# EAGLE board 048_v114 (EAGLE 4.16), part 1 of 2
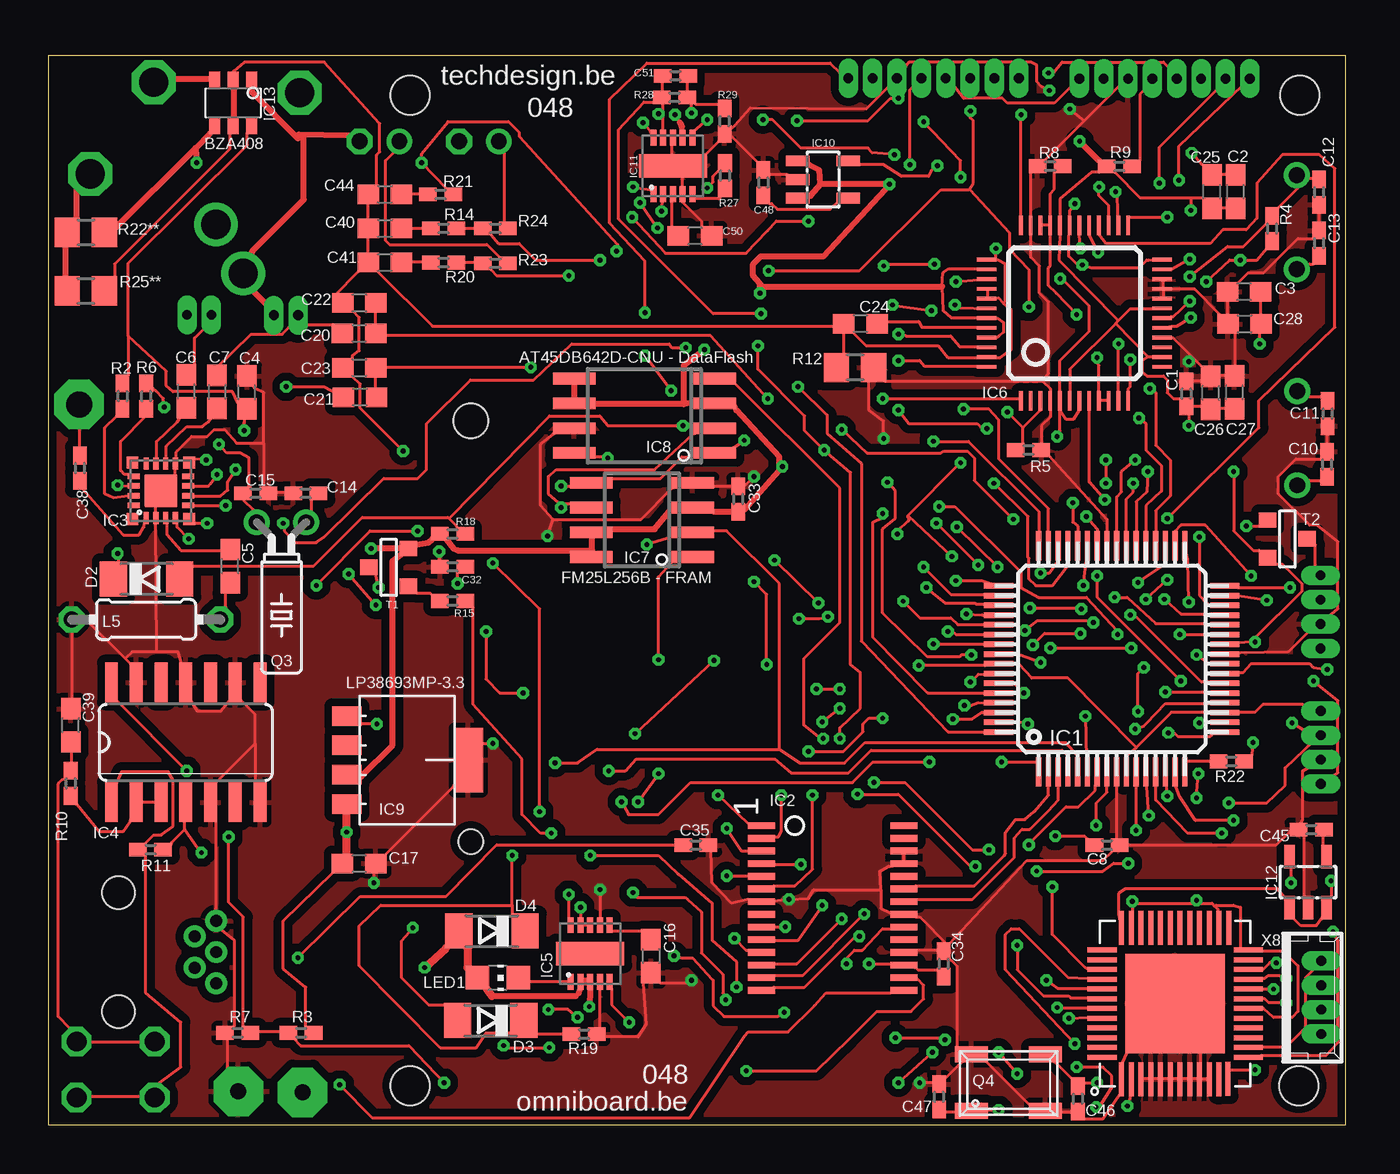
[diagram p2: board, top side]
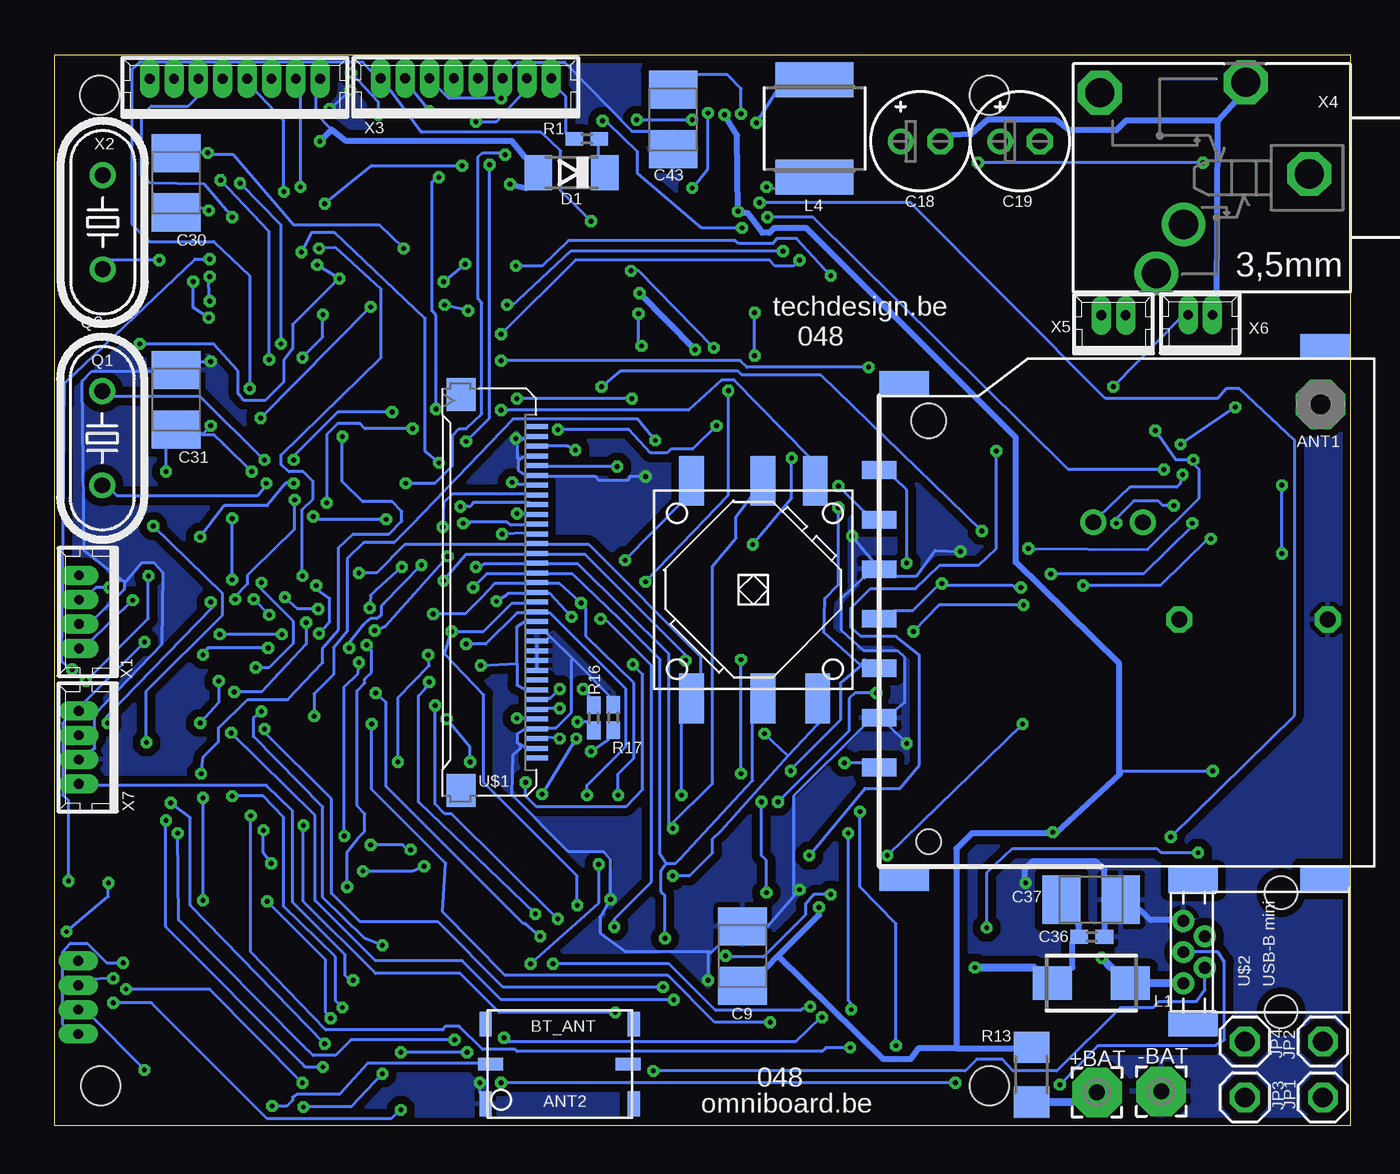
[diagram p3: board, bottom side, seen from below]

Size 66.5 x 54.9 mm. Coordinates in mm from the lower left corner, seen from the top.
Outline: 0,54.9 66.5,54.9 66.5,0 0,0 0,54.9
Copper layers (1*16): Top 0.0175mm / dielectric 1.55mm / Bottom 0.0175mm
Design rules "michel24": minimum track width 0.15mm, minimum drill 0.25mm, track to track 0.15mm, track to pad 0.15mm, pad to pad 0.2mm, via to via 0.2mm, smd to smd 0mil, copper to edge 0.25mm, drill to drill 0.1mm, minimum pad ring 10mil, minimum via ring 7mil, stop-mask expansion 2mil, vias tented up to drill 0mil, thermal gap 10mil
Holes 2 mm at 64.18,52.83 64.13,2.03 18.53,52.83 18.53,2.03

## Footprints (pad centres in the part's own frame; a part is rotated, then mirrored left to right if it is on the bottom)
2,54/0,8 = drill 0.813 pad 2.54 octagon: 1 0,0
PAD-01 = drill 1.321 pad 2.54 octagon: 1 0,0
BTANT_PAC = smd 1.27 x 0.635: P$1 0.7,-0.1; P$3 4.8,-0.1; P$4 4.8,7.5; P$6 0.7,7.5 | smd 0.635 x 1.27: P$2 2.75,0.15; P$5 2.75,7.2
C0402 = smd 0.9 x 0.7: 1 -0.65,0; 2 0.65,0
C0603 = smd 1.1 x 1: 1 -0.85,0; 2 0.85,0
B/3528-21R = smd 1.95 x 2.5: + 1.525,0; - -1.525,0
E2-5 = drill 0.813 pad 1.27 round: + -1.016,0 | drill 0.813 pad 1.27 octagon: - 1.016,0
SOD80C = smd 1.4 x 1.8: A 1.7,0; C -1.7,0
TQFP64-10X10 = smd 1.5 x 0.28: 1 -5.8,3.75; 2 -5.8,3.25; 3 -5.8,2.75; 4 -5.8,2.25; 5 -5.8,1.75; 6 -5.8,1.25; 7 -5.8,0.75; 8 -5.8,0.25; 9 -5.8,-0.25; 10 -5.8,-0.75; 11 -5.8,-1.25; 12 -5.8,-1.75; 13 -5.8,-2.25; 14 -5.8,-2.75; 15 -5.8,-3.25; 16 -5.8,-3.75; 33 5.8,-3.75; 34 5.8,-3.25; 35 5.8,-2.75; 36 5.8,-2.25; 37 5.8,-1.75; 38 5.8,-1.25; 39 5.8,-0.75; 40 5.8,-0.25; 41 5.8,0.25; 42 5.8,0.75; 43 5.8,1.25; 44 5.8,1.75; 45 5.8,2.25; 46 5.8,2.75; 47 5.8,3.25; 48 5.8,3.75 | smd 0.28 x 1.5: 17 -3.75,-5.8; 18 -3.25,-5.8; 19 -2.75,-5.8; 20 -2.25,-5.8; 21 -1.75,-5.8; 22 -1.25,-5.8; 23 -0.75,-5.8; 24 -0.25,-5.8; 25 0.25,-5.8; 26 0.75,-5.8; 27 1.25,-5.8; 28 1.75,-5.8; 29 2.25,-5.8; 30 2.75,-5.8; 31 3.25,-5.8; 32 3.75,-5.8; 49 3.75,5.8; 50 3.25,5.8; 51 2.75,5.8; 52 2.25,5.8; 53 1.75,5.8; 54 1.25,5.8; 55 0.75,5.8; 56 0.25,5.8; 57 -0.25,5.8; 58 -0.75,5.8; 59 -1.25,5.8; 60 -1.75,5.8; 61 -2.25,5.8; 62 -2.75,5.8; 63 -3.25,5.8; 64 -3.75,5.8
SSOP28DB = smd 0.348 x 1.397: 1 -4.225,-3.656; 2 -3.575,-3.656; 3 -2.925,-3.656; 4 -2.275,-3.656; 5 -1.625,-3.656; 6 -0.975,-3.656; 7 -0.325,-3.656; 8 0.325,-3.656; 9 0.975,-3.656; 10 1.625,-3.656; 11 2.275,-3.656; 12 2.925,-3.656; 13 3.575,-3.656; 14 4.225,-3.656; 15 4.225,3.656; 16 3.575,3.656; 17 2.925,3.656; 18 2.275,3.656; 19 1.625,3.656; 20 0.975,3.656; 21 0.325,3.656; 22 -0.325,3.656; 23 -0.975,3.656; 24 -1.625,3.656; 25 -2.275,3.656; 26 -2.925,3.656; 27 -3.575,3.656; 28 -4.225,3.656
QFN20-3X3 = smd 0.6 x 0.6: 1 -1.45,1.45; 6 -1.45,-1.45; 11 1.45,-1.45; 16 1.45,1.45 | smd 0.61 x 0.28: 2 -1.4,0.75; 3 -1.4,0.25; 4 -1.4,-0.25; 5 -1.4,-0.75; 12 1.4,-0.75; 13 1.4,-0.25; 14 1.4,0.25; 15 1.4,0.75 | smd 0.28 x 0.61: 7 -0.75,-1.4; 8 -0.25,-1.4; 9 0.25,-1.4; 10 0.75,-1.4; 17 0.75,1.4; 18 0.25,1.4; 19 -0.25,1.4; 20 -0.75,1.4 | smd 1.7 x 1.7: 21 0,0
SO14 = smd 0.66 x 2.032: 1 -3.81,-3.073; 2 -2.54,-3.073; 3 -1.27,-3.073; 4 0,-3.073; 5 1.27,-3.073; 6 2.54,-3.073; 7 3.81,-3.073; 8 3.81,3.073; 9 2.54,3.073; 10 1.27,3.073; 11 0,3.073; 12 -1.27,3.073; 13 -2.54,3.073; 14 -3.81,3.073
QFN10-3X3 = smd 0.813 x 0.305: 1 -1.45,1; 2 -1.45,0.5; 3 -1.45,0; 4 -1.45,-0.5; 5 -1.45,-1; 6 1.45,-1; 7 1.45,-0.5; 8 1.45,0; 9 1.45,0.5; 10 1.45,1 | smd 1.2 x 3.5: P$1 0,0
LQFP-48 = smd 0.2 x 1: 1 -2.75,-4.5; 2 -2.25,-4.5; 3 -1.75,-4.5; 4 -1.25,-4.5; 5 -0.75,-4.5; 6 -0.25,-4.5; 7 0.25,-4.5; 8 0.75,-4.5; 9 1.25,-4.5; 10 1.75,-4.5; 11 2.25,-4.5; 12 2.75,-4.5; 25 2.75,4.5; 26 2.25,4.5; 27 1.75,4.5; 28 1.25,4.5; 29 0.75,4.5; 30 0.25,4.5; 31 -0.25,4.5; 32 -0.75,4.5; 33 -1.25,4.5; 34 -1.75,4.5; 35 -2.25,4.5; 36 -2.75,4.5 | smd 1 x 0.2: 13 4.5,-2.75; 14 4.5,-2.25; 15 4.5,-1.75; 16 4.5,-1.25; 17 4.5,-0.75; 18 4.5,-0.25; 19 4.5,0.25; 20 4.5,0.75; 21 4.5,1.25; 22 4.5,1.75; 23 4.5,2.25; 24 4.5,2.75; 37 -4.5,2.75; 38 -4.5,2.25; 39 -4.5,1.75; 40 -4.5,1.25; 41 -4.5,0.75; 42 -4.5,0.25; 43 -4.5,-0.25; 44 -4.5,-0.75; 45 -4.5,-1.25; 46 -4.5,-1.75; 47 -4.5,-2.25; 48 -4.5,-2.75
SO-8 = smd 0.6 x 2.2: 1 -1.905,-2.6; 2 -0.635,-2.6; 3 0.635,-2.6; 4 1.905,-2.6; 5 1.905,2.6; 6 0.635,2.6; 7 -0.635,2.6; 8 -1.905,2.6
SO-8W = smd 0.6 x 2.2: 1 0.095,0.9; 2 1.365,0.9; 3 2.635,0.9; 4 3.905,0.9; 5 3.905,8.1; 6 2.635,8.1; 7 1.365,8.1; 8 0.095,8.1
SOT223-5 = smd 1 x 1.5: P$1 1.05,-0.65; P$2 2.55,-0.65; P$3 4.05,-0.65; P$4 5.55,-0.65 | smd 3.3 x 1.5: P$5 3.3,5.57
SOT23-5 = smd 0.55 x 1.2: 1 -0.95,-1.3; 2 0,-1.3; 3 0.95,-1.3; 4 0.95,1.3; 5 -0.95,1.3
SOT-457 = smd 0.55 x 0.8: 1 -0.95,-1.2; 2 0,-1.2; 3 0.95,-1.2; 4 0.95,1.2; 5 0,1.2; 6 -0.95,1.2
BGB203 = smd 1.75 x 0.25: 1 -3.88,2.75; 2 -3.88,2.25; 3 -3.88,1.75; 4 -3.88,1.25; 5 -3.88,0.75; 6 -3.88,0.25; 7 -3.88,-0.25; 8 -3.88,-0.75; 9 -3.88,-1.25; 10 -3.88,-1.75; 11 -3.88,-2.25; 12 -3.87,-2.71; 25 3.88,-2.75; 26 3.88,-2.25; 27 3.88,-1.75; 28 3.88,-1.25; 29 3.88,-0.75; 30 3.88,-0.25; 31 3.88,0.25; 32 3.88,0.75; 33 3.88,1.25; 34 3.88,1.75; 35 3.88,2.25; 36 3.88,2.75 | smd 0.25 x 1.5: 13 -2.75,-3.75; 14 -2.25,-3.75; 15 -1.75,-3.75; 16 -1.25,-3.75; 17 -0.75,-3.75; 18 -0.25,-3.75; 19 0.25,-3.75; 20 0.75,-3.75; 21 1.25,-3.75; 22 1.75,-3.75; 23 2.25,-3.75; 24 2.75,-3.75; 37 2.75,3.75; 38 2.25,3.75; 39 1.75,3.75; 40 1.25,3.75; 41 0.75,3.75; 42 0.25,3.75; 43 -0.25,3.75; 44 -0.75,3.75; 45 -1.25,3.75; 46 -1.75,3.75; 47 -2.25,3.75; 48 -2.75,3.75 | smd 5.1 x 5.1: 49 -0.002,0.007
1X01 = drill 1.016 octagon: 1 0,0
SM-B5 = smd 2 x 1.7: 1 -2,0; 2 2,0
L5650M = smd 1.8 x 4: 1 -2.5,0; 2 2.5,0
0204/7 = drill 0.813 octagon: 1 -3.81,0; 2 3.81,0
CHIP-LED0805 = smd 1.2 x 1.2: A 0,-1.05; C 0,1.05
HC49/S = drill 0.813 round: 1 -2.413,0; 2 2.413,0
TC26H = drill 0.813 round: 1 -1.27,0; 2 1.27,0
X-ABM3B_PACK = smd 1.676 x 0.813: P$1 0.6,0.2; P$2 4.4,0.2; P$3 4.4,3.1; P$4 0.6,3.1
R0402 = smd 0.9 x 0.7: 1 -0.65,0; 2 0.65,0
R0805 = smd 1.3 x 1.5: 1 -0.95,0; 2 0.95,0
R1206 = smd 1.6 x 1.8: 1 -1.4,0; 2 1.4,0
SOT-23 = smd 0.787 x 0.889: 1 0.025,-1.016; 2 -0.94,1.016; 3 0.991,1.016
XF2M-PAC = smd 1.1 x 0.25: 1 2.54,-8.52; 2 2.54,-8.02; 3 2.54,-7.52; 4 2.54,-7.02; 5 2.54,-6.52; 6 2.54,-6.02; 7 2.54,-5.52; 8 2.54,-5.02; 9 2.54,-4.52; 10 2.54,-4.02; 11 2.54,-3.52; 12 2.54,-3.02; 13 2.54,-2.52; 14 2.54,-2.02; 15 2.54,-1.52; 16 2.54,-1.02; 17 2.54,-0.52; 18 2.54,-0.02; 19 2.54,0.48; 20 2.54,0.98; 21 2.54,1.48; 22 2.54,1.98; 23 2.54,2.48; 24 2.54,2.98; 25 2.54,3.48; 26 2.54,3.98; 27 2.54,4.48; 28 2.54,4.98; 29 2.54,5.48; 30 2.54,5.98; 31 2.54,6.48; 32 2.54,6.98; 33 2.54,7.48; 34 2.54,7.98; 35 2.54,8.48 | smd 1.5 x 1.7: M1 -1.36,10.13; M2 -1.36,-10.17
USB-MINI-B-TH4 = drill 0.61 pad 1.016 round: P$1 1.448,8.51; P$2 2.248,7.41; P$3 3.048,8.51; P$4 3.848,7.41; P$5 4.648,8.51 | smd 1.27 x 2.54: P$8 -0.635,8.001; P$9 6.731,8.001 | hole 1.676: 0,3.5; 6.1,3.5
TACT2_PACK = smd 2.54 x 1.27: 1 -5.58,3.175; 2 -5.58,-0.5; 3 -5.58,-3.31; 4 5.58,-3.175; 5 5.58,-0.5; 6 5.58,3.175
MMC-SD-PACK3 = smd 1.27 x 2.54: P$1 -0.635,2.54; P$2 26.67,2.54; P$3 24.765,24.13; P$11 -0.635,24.13 | smd 0.914 x 1.778: P$4 20.32,25.4; P$5 17.78,25.4; P$6 15.24,25.4; P$7 12.7,25.4; P$8 10.16,25.4; P$9 7.62,25.4; P$10 5.08,25.4 | hole 1.27: 1.27,22.86 | hole 1.778: 22.86,22.86
53047-04 = drill 0.5 pad 0.698 long: 1 1.875,0.45; 2 0.625,0.45; 3 -0.625,0.45; 4 -1.875,0.45
53047-08 = drill 0.5 pad 0.698 long: 1 4.375,0.45; 2 3.125,0.45; 3 1.875,0.45; 4 0.625,0.45; 5 -0.625,0.45; 6 -1.875,0.45; 7 -3.125,0.45; 8 -4.375,0.45
PG203J = drill 1.499 octagon: 1 -5.004,-0.203; 4 5.74,-4.369; 5 -1.753,-4.902 | drill 1.499 round: 2 2.845,4.902; 3 1.448,2.388
53047-02 = drill 0.5 pad 0.698 long: 1 0.625,0.45; 2 -0.625,0.45

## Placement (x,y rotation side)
+BAT  [2,54/0,8]  13.02,1.68 270 bottom
-BAT  [2,54/0,8]  9.72,1.73 90 bottom
ANT1  [PAD-01]  1.56,36.97 0 bottom
ANT2  BT_ANT  [BTANT_PAC]  44.28,5.89 270 bottom
C1  100n  [C0402]  58.36,37.52 270 top
C2  100n  [C0603]  60.88,47.89 90 top
C3  100n  [C0603]  61.32,42.76 0 top
C4  100n  [C0603]  10.17,37.59 90 top
C5  470n  [C0603]  9.31,28.68 90 top
C6  330n  [C0603]  7.06,37.64 90 top
C7  330n  [C0603]  8.63,37.62 270 top
C8  100n  [C0402]  54.29,14.37 180 top
C9  4µ7/25V  [B/3528-21R]  31.2,8.68 270 bottom
C10  22p  [C0402]  65.58,33.9 270 top
C11  22p  [C0402]  65.6,36.51 90 top
C12  22p  [C0402]  65.17,47.86 90 top
C13  22p  [C0402]  65.17,45.25 270 top
C14  22p  [C0402]  13.19,32.42 0 top
C15  22p  [C0402]  10.62,32.41 180 top
C16  100n  [C0603]  30.89,8.67 270 top
C17  1µ  [C0603]  15.92,13.42 180 top
C18  100µ  [E2-5]  22.07,50.47 0 bottom
C19  100µ  [E2-5]  16.97,50.47 0 bottom
C20  1µ  [C0603]  15.92,40.62 0 top
C21  1µ  [C0603]  15.97,37.35 180 top
C22  10n  [C0603]  15.94,42.18 180 top
C23  10n  [C0603]  15.94,38.85 0 top
C24  1µ  [C0603]  41.64,41.12 0 top
C25  100n  [C0603]  59.67,47.89 90 top
C26  100n  [C0603]  59.61,37.57 90 top
C27  100n  [C0603]  60.83,37.59 90 top
C28  100n  [C0603]  61.34,41.1 0 top
C30  10µ  [B/3528-21R]  60.26,48.35 270 bottom
C31  10µ  [B/3528-21R]  60.25,37.2 270 bottom
C32  100n  [C0402]  20.72,28.64 180 top
C33  100n  [C0402]  35.37,32.12 90 top
C34  100n  [C0402]  45.91,8.27 270 top
C35  10n  [C0402]  33.19,14.36 0 top
C36  100n  [C0402]  13.29,9.66 0 bottom
C37  4µ7  [B/3528-21R]  13.31,11.57 180 bottom
C38  100p  [C0402]  1.6,33.7 90 top
C39  100n  [C0603]  1.13,20.51 90 top
C40  10n  [C0603]  17.25,46 0 top
C41  10n  [C0603]  17.25,44.25 0 top
C43  4µ7/25V  [B/3528-21R]  34.76,51.59 90 bottom
C44  47n  [C0603]  17.25,47.75 0 top
C45  10n  [C0402]  64.76,15.16 180 top
C46  6p7  [C0402]  52.79,1.36 270 top
C47  6p7  [C0402]  45.67,1.45 90 top
C48  10n  [C0402]  36.66,48.35 90 top
C50  47n  [C0603]  33.15,45.62 180 top
C51  33p  [C0402]  32.15,53.82 0 top
D1  1N4148  [SOD80C]  39.97,48.87 180 bottom
D2  1N4148  [SOD80C]  5.02,28.02 0 top
D3  1N4148  [SOD80C]  22.67,5.37 180 top
D4  1N4148  [SOD80C]  22.73,9.96 180 top
IC1  DSPIC33FJ256GP506/PT  [TQFP64-10X10]  54.53,23.92 90 top
IC2  FT245RL  [SSOP28DB]  40.22,11.14 270 top
IC3  SI4731  [QFN20-3X3]  5.75,32.54 90 top
IC4  74HC04D  [SO14]  7.03,19.64 0 top
IC5  MCP73855  [QFN10-3X3]  27.77,8.81 90 top
IC6  VS1053  [LQFP-48]  52.62,41.65 0 top
IC7  FM25L256B - FRAM  [SO-8]  30.43,31.05 90 top
IC8  AT45DB642D-CNU - DataFlash  [SO-8W]  35.06,34.39 90 top
IC9  LP38693MP-3.3  [SOT223-5]  15.95,22.03 270 top
IC10  LP2985IM5-1.8  [SOT23-5]  39.72,48.51 270 top
IC11  TPS61080  [QFN10-3X3]  32.02,49.21 90 top
IC12  LP2985IM5-2.8  [SOT23-5]  64.6,12.47 0 top
IC13  BZA408  [SOT-457]  9.46,52.44 180 top
IC14  BGB203_BLUETOOTHSMD  [BGB203]  57.78,6.24 90 top
JP1  [1X01]  1.43,1.42 180 bottom
JP2  [1X01]  1.43,4.29 180 bottom
JP3  [1X01]  5.43,1.42 180 bottom
JP4  [1X01]  5.43,4.29 180 bottom
L1  FERRITE BEAD  [SM-B5]  13.31,7.29 180 bottom
L4  4µH7  [L5650M]  27.5,51.14 90 bottom
L5  ferrite loop stick 180-600µH  [0204/7]  4.99,25.94 180 top
LED1  [CHIP-LED0805]  23.03,7.56 270 top
Q1  40MhZ  [HC49/S]  64.05,35.24 270 bottom
Q2  25MhZ  [HC49/S]  64.02,46.32 90 bottom
Q3  32768kHZ  [TC26H]  11.94,30.93 180 top
Q4  13MhZ  [X-ABM3B_PACK]  46.73,0.53 0 top
R1  10k  [R0402]  39.19,50.59 0 bottom
R2  10k  [R0402]  3.79,37.4 90 top
R3  470k  [R0402]  12.94,4.74 0 top
R4  1M  [R0402]  62.75,46 270 top
R5  100k  [R0402]  50.26,34.63 0 top
R6  2k2  [R0402]  5,37.4 90 top
R7  180k  [R0402]  9.69,4.74 0 top
R8  100k  [R0402]  51.37,49.2 180 top
R9  100k  [R0402]  54.92,49.18 180 top
R10  100k  [R0402]  1.13,17.54 90 top
R11  10k  [R0402]  5.22,14.13 180 top
R12  0R / 1206  [R0805]  41.36,38.87 180 top
R13  0R / 1206  [R1206]  16.37,2.59 270 bottom
R14  22R  [R0402]  20.25,46 0 top
R15  10k  [R0402]  20.72,26.89 0 top
R16  10k  [R0402]  38.83,20.9 90 bottom
R17  68k  [R0402]  37.83,20.91 270 bottom
R18  10k  [R0402]  20.71,30.33 180 top
R19  100k  [R0402]  27.46,4.67 0 top
R20  22R  [R0402]  20.25,44.25 0 top
R21  10R  [R0402]  20.1,47.75 0 top
R22  10k  [R0402]  60.66,18.66 180 top
R22**  0R  [R0805]  1.9,45.8 0 top
R23  10R  [R0402]  22.91,44.21 180 top
R24  10R  [R0402]  22.91,46.01 180 top
R25**  0R  [R0805]  1.9,42.8 0 top
R27  100R  [R0402]  34.69,48.7 270 top
R28  470k  [R0402]  32.1,52.72 180 top
R29  47k  [R0402]  34.67,51.51 90 top
T1  FMMT717  [SOT-23]  17.44,28.64 270 top
T2  FMMT717  [SOT-23]  63.54,30.05 90 top
U$1  OLED connector XF2M-3515-1  [XF2M-PAC]  44.28,27.35 0 bottom
U$2  USB-B mini  [USB-MINI-B-TH4]  0.08,5.83 90 bottom
U$3  TACT2_DEV  [TACT2_PACK]  30.65,27.47 90 bottom
U$4  SD-MMC socket  [MMC-SD-PACK3]  -1.21,13.28 90 bottom
X1  RS232-2  [53047-04]  64.79,26.33 90 bottom
X2  VS i/o  [53047-08]  57.24,53.24 0 bottom
X3  ICSP+  [53047-08]  45.39,53.26 0 bottom
X4  PG203J  [PG203J]  7.13,48.6 180 bottom
X5  53047-02  [53047-02]  12.17,41.1 0 bottom
X6  53047-02  [53047-02]  7.72,41.12 0 bottom
X7  RS232-1  [53047-04]  64.8,19.38 90 bottom
X8  53047-04  [53047-04]  64.83,6.55 270 top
